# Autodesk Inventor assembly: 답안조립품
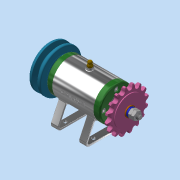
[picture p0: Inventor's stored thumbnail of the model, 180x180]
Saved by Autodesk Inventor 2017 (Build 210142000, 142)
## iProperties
Part Number: 답안조립품
Material: 일반
Document SubType Name: Assembly
Designer: Administrator
Author: Administrator
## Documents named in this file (16)
- C:\Users\Administrator\Desktop\711206V1012\답안조립품.iam
- C:\Users\Administrator\Desktop\711206V1012\본체.ipt
- C:\Users\Administrator\Desktop\711206V1012\V벨트풀리.ipt
- C:\Users\Administrator\Desktop\711206V1012\너트 M8.ipt
- C:\Users\Administrator\Desktop\711206V1012\니플 M6 x 0.75.ipt
- C:\Users\Administrator\Desktop\711206V1012\베어링 6002.ipt
- C:\Users\Administrator\Desktop\711206V1012\볼트 M4 x 12.ipt
- C:\Users\Administrator\Desktop\711206V1012\볼트 M6 x 8.ipt
- C:\Users\Administrator\Desktop\711206V1012\스프로킷.ipt
- C:\Users\Administrator\Desktop\711206V1012\스프링와셔 8.ipt
- C:\Users\Administrator\Desktop\711206V1012\오일 실 15 x 25 x 7.ipt
- C:\Users\Administrator\Desktop\711206V1012\와셔 6 x 11.5.ipt
- C:\Users\Administrator\Desktop\711206V1012\와셔 8 x 17.ipt
- C:\Users\Administrator\Desktop\711206V1012\축.ipt
- C:\Users\Administrator\Desktop\711206V1012\커버.ipt
- C:\Users\Administrator\Desktop\711206V1012\키 3 x 3.ipt
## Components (11 placed, 3 different names)
1. V벨트풀리:1
2. KS B 2023 6002 - 15 x 32 x 9:1
3. KS B 2023 6002 - 15 x 32 x 9:2
4. ISO 4762 M4 x 12:1 — 각도:1
5. ISO 4762 M4 x 12:3
6. ISO 4762 M4 x 12:4
7. ISO 4762 M4 x 12:5
8. ISO 4762 M4 x 12:2 — 각도:2
9. ISO 4762 M4 x 12:6
10. ISO 4762 M4 x 12:7
11. ISO 4762 M4 x 12:8
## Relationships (2: Angle 2)
- 각도:1 [Angle]: ISO 4762 M4 x 12:1
- 각도:2 [Angle]: ISO 4762 M4 x 12:2
